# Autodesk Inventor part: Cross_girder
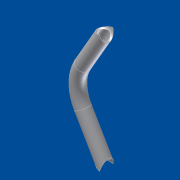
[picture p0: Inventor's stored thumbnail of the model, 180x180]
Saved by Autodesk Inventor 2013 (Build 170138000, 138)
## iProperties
Shininess: 69.0
Length Units: 11269
Angle Units: 11279
Time Units: 11290
Mass Units: 11283
Length Display Precision: 3
Angle Display Precision: 2
Created: 2001-04
Part Number: Cross_girder
Material: Standard
Document SubType Name: Modellieren
Designer: dl
Density: 1 g/cm^3
Density: 0.0
Volumn: 0.0
Area: 0.0
PropertySet Name: Model Information
Control State: 0
Master: False
Checked Out: False
Author: dl
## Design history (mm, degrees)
sketch "Sketch3"
  geometry: C1 r 9.5 at (88.621, 0) reference; A1 r 12.5 centre (88.621, 0) between (90.621, 12.339) and (90.621, -12.339)
  constraints: 2 point on circle, 1 centre point
  dimensions: "d24" = 12.5 radius of A1; "d25" = 0 distance of C1.centre A1.centre; "d26" = 0 distance of C1.centre A1.centre; "d29" = 2 horizontal distance of A1.start A1.centre; "d30" = 0 horizontal distance of A1.end A1.start
extrude "Extrusion1" sketch "Sketch3" dims "d27" = 30, "d28" = 0
body "Solid1"
workaxis "Work Axis1"
workplane "Work Plane1"
sweep "Sweep1" dims "d21" = 0
workaxis "Work Axis2"
workplane "Work Plane2"
sketch "Sketch4"
  geometry: C1 r 9.495 at (0, 0) reference; C2 r 12.495 at (0, 0) reference
extrude "Extrusion2" join sketch "Sketch4" stored distance "d31" = 30; taper "d32" = 0 deg
mirror "Mirror1"
sketch "Sketch1"
  geometry: L1 (-254.622, 47.452)-(-292.122, -17.5); L2 (-292.122, -87.5)-(-254.622, -152.452); L3 (-330.1, -52.5)-(70.3, -52.5) reference; L4 (-15.5, 12.5)-(-15.5, -12.5) reference; A1 r 70 centre (-231.5, -52.5) between (-292.122, -17.5) and (-292.122, -87.5)
  constraints: 4 end point, 2 point on circle, 2 tangent, 1 centre point, 1 equal length
  dimensions: "d0" = 70 radius of A1; "d1" = 0 distance from line of L3 A1.centre; "d2" = 216 horizontal distance of A1.centre L4.end (computed from d0); "d3" = 120 deg angle of L2 L1; "d4" = 60 deg angle of L1 L3 (= 0.5 x d3); "d5" = 75 distance of L2.start L2.end
sketch "Sketch2"
  geometry: L1 (-297.122, 0)-(-306.5, 0) reference; C1 r 12.495 at (-306.5, 0); C2 r 9.495 at (-306.5, 0); 1 further point
  constraints: 2 centre point, 2 coincident
  dimensions: "d19" = 24.99 diameter of C1; "d20" = 3 radial gap between concentric circles of C1 C2
body "Srf1"
other parameters: "d6" = 90 deg, "d22" = 90 deg, "d23" = 90 deg
